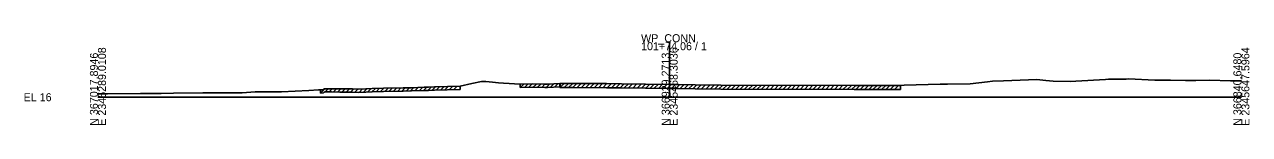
# Model space of a CAD drawing. Extents: x -26 to 2345577, y -10 to 367097.
# Drawn here: x -25.7 to 402.8, y 990.3 to 1022.1 of the extents above; entities that cross this region are included whole.
import ezdxf

# ---------------------------------------------------------------- set-up
doc = ezdxf.new("R2010")
doc.units = 0
for name, color, linetype in [('RD_GPK_XS_Cell', 7, 'Continuous'), ('RD_XS_ExGround', 7, 'Continuous'), ('RD_XS_ExPaveRet', 7, 'Continuous')]:
    doc.layers.add(name, color=color, linetype=linetype)

msp = doc.modelspace()

# ---------------------------------------------------------------- linework, layer by layer
at = {"layer": 'RD_GPK_XS_Cell'}
for p, q in [((200, 1000), (200, 1019.27)), ((0, 1000), (200, 1000)), ((200, 1000), (400, 1000))]:
    msp.add_line(p, q, dxfattribs=at)
at = {"layer": 'RD_XS_ExGround'}
msp.add_lwpolyline([(0, 1001.19), (3.3, 1001.21), (14.91, 1001.3), (17.77, 1001.33), (22.09, 1001.36), (26.42, 1001.44), (36.67, 1001.49), (37.74, 1001.49), (48.94, 1001.55), (50.51, 1001.58), (55.05, 1001.83), (64.16, 1001.92), (73.79, 1002.34), (77.14, 1002.57), (77.83, 1002.6), (78.95, 1002.62), (79.11, 1002.88), (79.5, 1002.99), (81.67, 1002.99), (84.57, 1002.92), (89.09, 1002.89), (91, 1002.84), (93.71, 1002.94), (95.94, 1003.02), (99.86, 1003.18), (106.81, 1003.3), (109.66, 1003.33), (114.14, 1003.47), (115.59, 1003.52), (117.73, 1003.58), (126.73, 1003.85), (130.81, 1004.85), (134.2, 1005.55), (135.69, 1005.45), (138.03, 1005.26), (140.13, 1005.01), (141.92, 1004.92), (147.76, 1004.55), (152.1, 1004.66), (156.3, 1004.56), (157.3, 1004.59), (161.63, 1004.81), (166.21, 1004.81), (177.95, 1004.75), (183.14, 1004.7), (200, 1004.49), (203.13, 1004.45), (208.87, 1004.37), (217.93, 1004.22), (264.56, 1004.16), (280.7, 1004.13), (281.99, 1004.21), (294.67, 1004.53), (297.18, 1004.58), (305.07, 1004.64), (311.13, 1005.44), (312.98, 1005.64), (316.77, 1005.79), (328.5, 1006.26), (331.62, 1005.83), (334.1, 1005.57), (340.39, 1005.56), (342.13, 1005.68), (352.52, 1006.25), (353.54, 1006.28), (359.71, 1006.36), (360.54, 1006.42), (369.75, 1005.95), (371.55, 1005.96), (373.04, 1005.95), (375.25, 1005.92), (380.49, 1005.84), (382.24, 1005.84), (384.1, 1005.9), (388.9, 1005.99), (396.16, 1005.73), (400, 1005.77)], dxfattribs=at)
at = {"layer": 'RD_XS_ExPaveRet'}
for p, q in [((77.85, 1001.46), (79.33, 1002.94)), ((79.35, 1001.8), (80.54, 1002.99)), ((80.85, 1001.85), (81.99, 1002.99)), ((82.35, 1001.83), (83.47, 1002.95)), ((83.85, 1001.8), (84.97, 1002.92)), ((85.35, 1001.78), (86.48, 1002.91)), ((86.85, 1001.76), (87.98, 1002.9)), ((88.35, 1001.75), (89.48, 1002.88)), ((89.85, 1001.73), (90.97, 1002.84)), ((91.35, 1001.71), (92.53, 1002.89)), ((92.85, 1001.76), (94.03, 1002.95)), ((94.35, 1001.82), (95.54, 1003)), ((95.85, 1001.87), (97.04, 1003.06)), ((97.35, 1001.93), (98.54, 1003.12)), ((98.85, 1001.99), (100.04, 1003.18)), ((100.35, 1002.04), (101.51, 1003.2)), ((101.85, 1002.07), (103.01, 1003.23)), ((103.35, 1002.09), (104.51, 1003.26)), ((104.85, 1002.12), (106.01, 1003.28)), ((106.35, 1002.15), (107.51, 1003.31)), ((107.85, 1002.17), (109.01, 1003.32)), ((109.35, 1002.19), (110.52, 1003.36)), ((110.85, 1002.23), (112.03, 1003.4)), ((112.35, 1002.27), (113.53, 1003.45)), ((113.85, 1002.32), (115.03, 1003.5)), ((115.35, 1002.37), (116.53, 1003.54)), ((116.85, 1002.41), (118.03, 1003.59)), ((118.35, 1002.45), (119.53, 1003.63)), ((119.85, 1002.5), (121.03, 1003.68)), ((121.35, 1002.54), (122.53, 1003.72)), ((122.85, 1002.59), (124.03, 1003.77)), ((124.35, 1002.64), (125.53, 1003.81)), ((126.73, 1003.85), (126.73, 1002.71)), ((147.76, 1003.41), (148.93, 1004.58)), ((147.76, 1003.41), (147.76, 1004.55)), ((147.76, 1003.41), (152.1, 1003.51)), ((149.26, 1003.44), (150.43, 1004.62)), ((150.76, 1003.48), (151.93, 1004.65)), ((152.1, 1003.51), (156.3, 1003.42)), ((152.26, 1003.51), (153.38, 1004.63)), ((153.76, 1003.47), (154.88, 1004.59)), ((155.26, 1003.44), (156.38, 1004.56)), ((156.3, 1003.42), (157.3, 1003.45)), ((156.76, 1003.43), (157.95, 1004.62)), ((157.3, 1003.45), (161.63, 1003.66)), ((158.26, 1003.5), (159.46, 1004.7)), ((159.76, 1003.57), (160.96, 1004.77)), ((161.63, 1003.37), (163.07, 1004.81)), ((161.63, 1003.37), (161.63, 1004.81)), ((161.63, 1003.66), (161.68, 1003.66)), ((161.63, 1003.37), (166.21, 1003.37)), ((161.68, 1004.81), (161.68, 1003.66)), ((163.13, 1003.37), (164.57, 1004.81)), ((164.63, 1003.37), (166.07, 1004.81)), ((166.13, 1003.37), (167.56, 1004.8)), ((166.21, 1003.37), (177.95, 1003.32)), ((167.63, 1003.37), (169.06, 1004.8)), ((169.13, 1003.36), (170.56, 1004.79)), ((170.63, 1003.35), (172.06, 1004.78)), ((172.13, 1003.34), (173.56, 1004.77)), ((173.63, 1003.34), (175.06, 1004.77)), ((175.13, 1003.33), (176.56, 1004.76)), ((176.63, 1003.32), (178.06, 1004.75)), ((177.95, 1003.32), (183.14, 1003.27)), ((178.13, 1003.31), (179.55, 1004.74)), ((179.63, 1003.3), (181.05, 1004.72)), ((181.13, 1003.29), (182.55, 1004.71)), ((182.63, 1003.27), (184.05, 1004.69)), ((183.14, 1003.27), (200, 1003.05)), ((184.13, 1003.25), (185.55, 1004.67)), ((185.63, 1003.23), (187.05, 1004.65)), ((187.13, 1003.22), (188.55, 1004.64)), ((188.63, 1003.2), (190.05, 1004.62)), ((190.13, 1003.18), (191.55, 1004.6)), ((191.63, 1003.16), (193.05, 1004.58)), ((193.13, 1003.14), (194.55, 1004.56)), ((194.63, 1003.12), (196.05, 1004.54)), ((196.13, 1003.1), (197.55, 1004.52)), ((197.63, 1003.08), (199.05, 1004.5)), ((199.13, 1003.07), (200.55, 1004.48)), ((200, 1003.05), (203.13, 1003.01)), ((200.63, 1003.05), (202.05, 1004.47)), ((202.13, 1003.03), (203.55, 1004.45)), ((203.13, 1003.01), (208.87, 1002.93)), ((203.63, 1003.01), (205.05, 1004.42)), ((205.13, 1002.99), (206.55, 1004.4)), ((206.63, 1002.96), (208.05, 1004.38)), ((208.13, 1002.94), (209.55, 1004.36)), ((208.87, 1002.93), (217.93, 1002.78)), ((209.63, 1002.92), (211.05, 1004.33)), ((211.13, 1002.89), (212.55, 1004.31)), ((212.63, 1002.87), (214.05, 1004.28)), ((214.13, 1002.85), (215.55, 1004.26)), ((215.63, 1002.82), (217.05, 1004.24)), ((217.13, 1002.8), (218.55, 1004.22)), ((217.93, 1002.78), (264.56, 1002.72)), ((218.63, 1002.78), (220.07, 1004.22)), ((220.13, 1002.78), (221.57, 1004.22)), ((221.63, 1002.78), (223.07, 1004.22)), ((223.13, 1002.78), (224.57, 1004.21)), ((224.63, 1002.78), (226.07, 1004.21)), ((226.13, 1002.77), (227.57, 1004.21)), ((227.63, 1002.77), (229.07, 1004.21)), ((229.13, 1002.77), (230.57, 1004.21)), ((230.63, 1002.77), (232.07, 1004.2)), ((232.13, 1002.77), (233.57, 1004.2)), ((233.63, 1002.76), (235.07, 1004.2)), ((235.13, 1002.76), (236.57, 1004.2)), ((236.63, 1002.76), (238.07, 1004.2)), ((238.13, 1002.76), (239.57, 1004.19)), ((239.63, 1002.76), (241.07, 1004.19)), ((241.13, 1002.75), (242.57, 1004.19)), ((242.63, 1002.75), (244.07, 1004.19)), ((244.13, 1002.75), (245.57, 1004.19)), ((245.63, 1002.75), (247.07, 1004.18)), ((247.13, 1002.75), (248.57, 1004.18)), ((248.63, 1002.75), (250.07, 1004.18)), ((250.13, 1002.74), (251.57, 1004.18)), ((251.63, 1002.74), (253.07, 1004.18)), ((253.13, 1002.74), (254.57, 1004.17)), ((254.63, 1002.74), (256.07, 1004.17)), ((256.13, 1002.74), (257.57, 1004.17)), ((257.63, 1002.73), (259.07, 1004.17)), ((259.13, 1002.73), (260.57, 1004.17)), ((260.63, 1002.73), (262.07, 1004.16)), ((262.13, 1002.73), (263.57, 1004.16)), ((263.63, 1002.73), (265.07, 1004.16)), ((265.13, 1002.72), (266.57, 1004.16)), ((266.63, 1002.72), (268.07, 1004.16)), ((268.13, 1002.72), (269.57, 1004.15)), ((269.63, 1002.72), (271.07, 1004.15)), ((271.13, 1002.71), (272.57, 1004.15)), ((272.63, 1002.71), (274.07, 1004.15)), ((274.13, 1002.71), (275.57, 1004.14)), ((275.63, 1002.71), (277.07, 1004.14)), ((277.13, 1002.7), (278.57, 1004.14)), ((278.63, 1002.7), (280.07, 1004.14)), ((280.71, 1004.14), (280.71, 1002.7)), ((77.85, 1001.46), (77.85, 1002.6)), ((77.85, 1001.46), (78.95, 1001.48)), ((78.95, 1001.48), (79.11, 1001.74)), ((79.11, 1001.74), (79.5, 1001.85)), ((79.5, 1001.85), (81.67, 1001.85)), ((81.67, 1001.85), (84.57, 1001.78)), ((84.57, 1001.78), (89.09, 1001.75)), ((89.09, 1001.75), (91, 1001.7)), ((91, 1001.7), (93.71, 1001.79)), ((93.71, 1001.79), (95.94, 1001.87)), ((95.94, 1001.87), (99.86, 1002.03)), ((99.86, 1002.03), (106.81, 1002.15)), ((106.81, 1002.15), (109.66, 1002.19)), ((109.66, 1002.19), (114.14, 1002.33)), ((114.14, 1002.33), (115.59, 1002.38)), ((115.59, 1002.38), (117.73, 1002.43)), ((117.73, 1002.43), (126.73, 1002.71)), ((264.56, 1002.72), (280.7, 1002.7)), ((280.7, 1002.7), (280.71, 1002.7))]:
    msp.add_line(p, q, dxfattribs=at)

# ---------------------------------------------------------------- texts
at = {"layer": 'RD_GPK_XS_Cell'}
for s, p in [('WP_CONN', (190, 1019.27)), ('101+74.06 / 1', (190, 1016.47)), ('EL 16', (-26, 998.6))]:
    msp.add_text(s, height=2.8, dxfattribs=at).set_placement(p)
for s, p in [('E 2345289.0108', (2.8, 990)), ('E 2345468.3036', (202.8, 990)), ('E 2345647.5964', (402.8, 990)), ('N 367017.8946', (0, 990)), ('N 366929.2713', (200, 990)), ('N 366840.6480', (400, 990))]:
    msp.add_text(s, height=2.8, rotation=90, dxfattribs=at).set_placement(p)

doc.saveas('drawing.dxf')
